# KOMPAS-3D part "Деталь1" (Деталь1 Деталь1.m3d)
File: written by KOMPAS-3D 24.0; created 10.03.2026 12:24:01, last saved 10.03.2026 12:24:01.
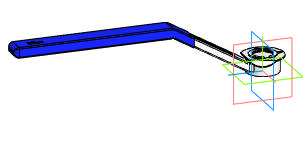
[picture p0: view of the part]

Document properties: Автор: R2D2; Полное имя файла: E:\Работа\Зайцев\BV3232P(4pc)-FP-3WL-F-ISO-H Кран шаровой DN.ru Ду15-100 Ру16\DN32\исходные материалы\Деталь1 Деталь1.m3d

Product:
- Body: Твердое тело1  | qty 1
- Part/product: Деталь1
    additional columns: Типовые

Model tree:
1. Твердое тело1  (labels: Твердое тело1)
